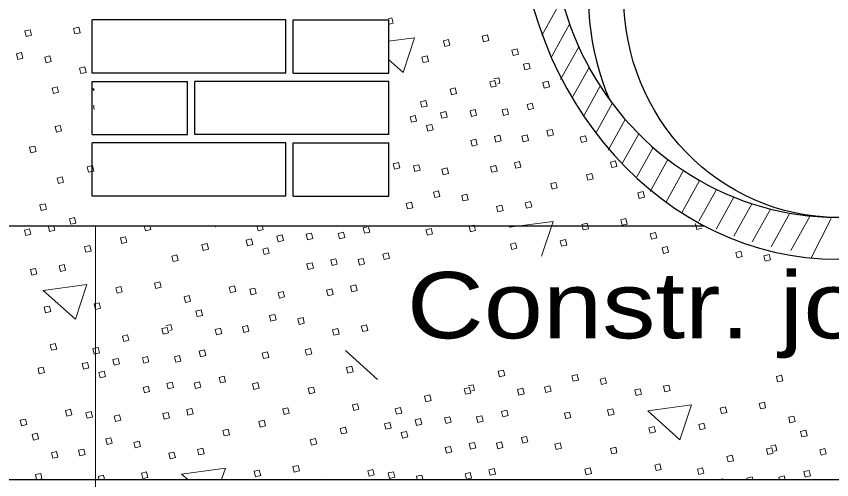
# Model space of a CAD drawing. Extents: x 750.7 to 784.7, y 860.1 to 882.1.
# Drawn here: x 761.813 to 763.779, y 862.952 to 864.07 of the extents above; entities that cross this region are included whole.
import ezdxf

# ---------------------------------------------------------------- set-up
doc = ezdxf.new("R2010")
doc.units = 0
doc.header["$LTSCALE"] = 0.064
doc.layers.add('1', color=7, linetype='Continuous', lineweight=13)

msp = doc.modelspace()

# ---------------------------------------------------------------- linework, layer by layer
at = {"layer": '1'}
for p, q in [((763.07975, 864.02367), (763.12817, 864.11092)), ((762.70967, 864.06392), (762.71867, 864.06608)), ((763.10242, 863.97033), (763.14692, 864.0505)), ((762.77325, 864.01792), (762.7095, 864.0095)), ((763.125, 863.91692), (763.16892, 863.996)), ((763.15492, 863.87667), (763.19367, 863.94642)), ((762.96383, 863.91883), (762.97592, 863.92167)), ((763.18183, 863.83092), (763.22075, 863.901)), ((763.21008, 863.78758), (763.24992, 863.85933)), ((763.23958, 863.74658), (763.28092, 863.82108)), ((763.274, 863.7145), (763.31367, 863.78592)), ((763.30875, 863.68283), (763.34808, 863.75367)), ((763.34125, 863.64733), (763.384, 863.72425)), ((763.37892, 863.621), (763.4215, 863.6975)), ((763.41792, 863.597), (763.46042, 863.6735)), ((763.45825, 863.5755), (763.50083, 863.65217)), ((763.49992, 863.55633), (763.54283, 863.63358)), ((763.54292, 863.53958), (763.58625, 863.61775)), ((763.58733, 863.52542), (763.63133, 863.60475)), ((763.63317, 863.51383), (763.67808, 863.59475)), ((763.107, 863.57508), (763.00158, 863.561)), ((763.07917, 863.49133), (763.107, 863.57508)), ((763.68058, 863.505), (763.72667, 863.58808)), ((763.72958, 863.48683), (763.77717, 863.582)), ((762.00408, 862.95208), (762.00408, 863.56433)), ((762.17367, 863.32342), (762.18583, 863.32625)), ((762.6065, 863.26333), (762.68408, 863.19367)), ((762.9025, 863.17825), (762.91458, 863.18108)), ((762.00408, 863.15042), (762.00408, 862.09025)), ((763.63125, 863.033), (763.64342, 863.03592)), ((762.02317, 862.96258), (762.02567, 862.95208)), ((762.30775, 862.95208), (762.31692, 862.97967)), ((762.79025, 862.96317), (762.79292, 862.95208)), ((762.55975, 862.95208), (762.56375, 862.953)), ((762.56375, 862.953), (762.564, 862.95208)), ((763.50742, 862.95208), (763.51608, 862.95417)), ((763.51608, 862.95417), (763.51658, 862.95208)), ((763.58708, 862.95883), (763.58867, 862.95208)), ((763.66417, 862.96108), (763.66633, 862.95208))]:
    msp.add_line(p, q, dxfattribs=at)
at = {"layer": '1', "lineweight": 25}
for p, q in [((762.71083, 863.93283), (762.71083, 864.06083)), ((762.48075, 863.93283), (762.71083, 863.93283)), ((762.22558, 863.7845), (762.22558, 863.91258)), ((761.9955, 863.7845), (762.22558, 863.7845)), ((762.71083, 863.63625), (762.71083, 863.76433)), ((762.48075, 863.63625), (762.71083, 863.63625)), ((760.59067, 863.56433), (763.47158, 863.56433)), ((760.59067, 862.95208), (765.58325, 862.95208))]:
    msp.add_line(p, q, dxfattribs=at)
at = {"layer": '1'}
for points in [[(762.71867, 864.06608), (762.72183, 864.05283), (762.70967, 864.04992)], [(762.70942, 863.96658), (762.74542, 863.93425), (762.77325, 864.01792)], [(762.97592, 863.92167), (762.97908, 863.90842), (762.97275, 863.90692)], [(762.00033, 863.89517), (761.99625, 863.89458), (762.00042, 863.89083)], [(762.00092, 863.84533), (761.99883, 863.85392), (762.00083, 863.85433)], [(761.9035, 863.5625), (761.90567, 863.55367), (761.89308, 863.55067), (761.89025, 863.5625)], [(762.1355, 863.56217), (762.13717, 863.55508), (762.12467, 863.55208), (762.12225, 863.56217)], [(762.29325, 863.56192), (762.29275, 863.56183), (762.29267, 863.56192)], [(762.40683, 863.56175), (762.40833, 863.5555), (762.39575, 863.55258), (762.39358, 863.56175)], [(762.66208, 863.56142), (762.665, 863.54933), (762.65242, 863.54633), (762.64925, 863.55958), (762.65692, 863.56142)], [(763.46592, 863.55875), (763.4535, 863.55583), (763.45033, 863.569), (763.45133, 863.56925)], [(762.18583, 863.32625), (762.189, 863.31308), (762.18267, 863.3115)], [(762.91458, 863.18108), (762.91775, 863.16783), (762.91142, 863.16633)], [(763.64342, 863.03592), (763.64658, 863.02267), (763.64025, 863.02108)], [(761.862, 862.95208), (761.85908, 862.96417), (761.87167, 862.96717)], [(761.87167, 862.96717), (761.87483, 862.95392), (761.86717, 862.95208)], [(762.01242, 862.95208), (762.01058, 862.95958), (762.02317, 862.96258)], [(762.31692, 862.97967), (762.2115, 862.96558), (762.2265, 862.95208)], [(762.77958, 862.95208), (762.77767, 862.96025), (762.79025, 862.96317)], [(763.57542, 862.95208), (763.5745, 862.95583), (763.58708, 862.95883)], [(763.65308, 862.95208), (763.65167, 862.95808), (763.66417, 862.96108)]]:
    msp.add_lwpolyline(points, dxfattribs=at)
at = {"layer": '1', "lineweight": 25}
for points in [[(762.46308, 863.93283), (762.46308, 864.06083), (761.99542, 864.06083)], [(762.46308, 863.93283), (761.99542, 863.93283), (761.99542, 864.06083)], [(762.48075, 863.93283), (762.48075, 864.06083), (762.71083, 864.06083)], [(761.9955, 863.7845), (761.9955, 863.91258), (762.22558, 863.91258)], [(762.71083, 863.7845), (762.71083, 863.91258), (762.24317, 863.91258)], [(762.71083, 863.7845), (762.24317, 863.7845), (762.24317, 863.91258)], [(762.46308, 863.63625), (762.46308, 863.76433), (761.99542, 863.76433)], [(762.46308, 863.63625), (761.99542, 863.63625), (761.99542, 863.76433)], [(762.48075, 863.63625), (762.48075, 863.76433), (762.71083, 863.76433)]]:
    msp.add_lwpolyline(points, dxfattribs=at)
at = {"layer": '1'}
for points in [[(761.84625, 864.03733), (761.84942, 864.02417), (761.83683, 864.02117), (761.83367, 864.03442)], [(761.9635, 864.04333), (761.96667, 864.03008), (761.95417, 864.02708), (761.95092, 864.04033)], [(762.94892, 864.02467), (762.95208, 864.01142), (762.93958, 864.00842), (762.93633, 864.02167)], [(762.85525, 864.01342), (762.85842, 864.00017), (762.84592, 863.99725), (762.84267, 864.01042)], [(763.02017, 863.99133), (763.02333, 863.97808), (763.01075, 863.97508), (763.00758, 863.98833)], [(761.82575, 863.98208), (761.829, 863.96892), (761.81642, 863.96592), (761.81325, 863.97908)], [(761.89392, 863.97408), (761.89708, 863.96083), (761.88458, 863.95783), (761.88133, 863.97108)], [(762.80317, 863.97425), (762.80642, 863.961), (762.79383, 863.958), (762.79067, 863.97125)], [(761.97792, 863.94775), (761.98108, 863.9345), (761.96858, 863.9315), (761.96533, 863.94475)], [(763.04867, 863.957), (763.05183, 863.94375), (763.03925, 863.94075), (763.03608, 863.954)], [(762.96683, 863.91483), (762.97, 863.90158), (762.95742, 863.89858), (762.95425, 863.91183)], [(763.09517, 863.913), (763.09833, 863.89975), (763.08575, 863.89675), (763.08258, 863.91)], [(761.91175, 863.89967), (761.915, 863.88642), (761.90242, 863.8835), (761.89925, 863.89667)], [(762.87133, 863.89692), (762.8745, 863.88367), (762.86192, 863.88067), (762.85875, 863.89392)], [(762.80017, 863.8665), (762.80342, 863.85325), (762.79083, 863.85025), (762.78767, 863.8635)], [(763.05683, 863.86025), (763.06, 863.847), (763.0475, 863.844), (763.04425, 863.85725)], [(762.77475, 863.83042), (762.77792, 863.81717), (762.76533, 863.81417), (762.76217, 863.82742)], [(762.84858, 863.83992), (762.85175, 863.82667), (762.83925, 863.82367), (762.836, 863.83692)], [(762.91958, 863.84458), (762.92275, 863.83133), (762.91025, 863.82833), (762.907, 863.84158)], [(762.99675, 863.84692), (762.99992, 863.83367), (762.98733, 863.83067), (762.98417, 863.84392)], [(762.81475, 863.80908), (762.81792, 863.79583), (762.80542, 863.79283), (762.80217, 863.80608)], [(761.91892, 863.80667), (761.92217, 863.7935), (761.90958, 863.7905), (761.90642, 863.80375)], [(763.1045, 863.797), (763.10775, 863.78375), (763.09517, 863.78075), (763.092, 863.794)], [(762.92108, 863.773), (762.92433, 863.75975), (762.91175, 863.75683), (762.90858, 863.77)], [(762.97867, 863.78267), (762.98183, 863.76942), (762.96925, 863.76642), (762.96608, 863.77967)], [(763.04442, 863.78358), (763.04758, 863.77033), (763.035, 863.76733), (763.03183, 863.78058)], [(763.18533, 863.78158), (763.1885, 863.76833), (763.17592, 863.76533), (763.17275, 863.77858)], [(761.8575, 863.75675), (761.86067, 863.7435), (761.84808, 863.7405), (761.84492, 863.75375)], [(761.99633, 863.70975), (761.99958, 863.69658), (761.987, 863.69358), (761.98383, 863.70683)], [(762.73408, 863.71725), (762.73725, 863.704), (762.72475, 863.701), (762.7215, 863.71425)], [(762.78342, 863.71183), (762.78658, 863.69858), (762.77408, 863.69558), (762.77083, 863.70883)], [(762.96883, 863.70975), (762.972, 863.6965), (762.95942, 863.6935), (762.95625, 863.70675)], [(763.02633, 863.71942), (763.0295, 863.70617), (763.017, 863.70317), (763.01375, 863.71642)], [(763.25783, 863.72083), (763.26108, 863.70758), (763.2485, 863.70467), (763.24533, 863.71783)], [(762.85158, 863.70383), (762.85475, 863.69058), (762.84217, 863.68758), (762.839, 863.70083)], [(763.20033, 863.69058), (763.20358, 863.67733), (763.191, 863.67433), (763.18783, 863.68758)], [(761.92375, 863.68267), (761.927, 863.66942), (761.91442, 863.66642), (761.91117, 863.67967)], [(763.11383, 863.66917), (763.117, 863.65592), (763.1045, 863.65292), (763.10125, 863.66617)], [(762.83108, 863.6485), (762.83433, 863.63533), (762.82175, 863.63233), (762.81858, 863.64558)], [(762.89925, 863.6405), (762.90242, 863.62725), (762.88983, 863.62425), (762.88667, 863.6375)], [(763.32417, 863.64675), (763.32733, 863.6335), (763.31475, 863.6305), (763.31158, 863.64375)], [(761.88225, 863.61767), (761.8855, 863.60442), (761.87292, 863.60142), (761.86975, 863.61467)], [(762.76558, 863.62125), (762.76875, 863.608), (762.75625, 863.60508), (762.753, 863.61825)], [(762.98325, 863.61417), (762.98642, 863.60092), (762.97383, 863.59792), (762.97067, 863.61117)], [(763.05242, 863.62317), (763.05558, 863.60992), (763.043, 863.607), (763.03983, 863.62017)], [(761.9535, 863.58433), (761.95667, 863.57108), (761.94417, 863.56808), (761.94092, 863.58133)], [(763.28267, 863.58175), (763.28583, 863.5685), (763.27333, 863.56558), (763.27008, 863.57875)], [(761.84492, 863.55725), (761.84817, 863.544), (761.83558, 863.541), (761.83242, 863.55425)], [(762.81325, 863.558), (762.8165, 863.54475), (762.80392, 863.54175), (762.80067, 863.555)], [(762.91708, 863.56608), (762.92033, 863.55292), (762.90775, 863.54992), (762.90458, 863.56317)], [(763.189, 863.57058), (763.19217, 863.55733), (763.17958, 863.55433), (763.17642, 863.56758)], [(762.0765, 863.53808), (762.07967, 863.52483), (762.06717, 863.52183), (762.06392, 863.53508)], [(762.37967, 863.53267), (762.38283, 863.51942), (762.37033, 863.51642), (762.36708, 863.52967)], [(762.4535, 863.54225), (762.45675, 863.529), (762.44417, 863.526), (762.441, 863.53925)], [(762.5245, 863.54692), (762.52767, 863.53367), (762.51517, 863.53067), (762.51192, 863.54392)], [(762.60167, 863.54917), (762.60483, 863.53592), (762.59225, 863.53292), (762.58908, 863.54617)], [(763.35392, 863.54842), (763.35708, 863.53517), (763.3445, 863.53217), (763.34133, 863.54542)], [(761.98992, 863.51667), (761.99317, 863.50342), (761.98058, 863.50042), (761.97742, 863.51367)], [(762.27292, 863.52142), (762.27608, 863.50817), (762.2635, 863.50517), (762.26033, 863.51842)], [(763.01675, 863.52333), (763.01992, 863.51008), (763.00742, 863.50708), (763.00417, 863.52033)], [(763.13692, 863.53133), (763.14017, 863.51808), (763.12758, 863.51508), (763.12442, 863.52833)], [(763.38242, 863.51408), (763.38558, 863.50083), (763.373, 863.49783), (763.36983, 863.51108)], [(762.20025, 863.49425), (762.2035, 863.481), (762.19092, 863.478), (762.18775, 863.49125)], [(762.41967, 863.51142), (762.42292, 863.49817), (762.41033, 863.49517), (762.40717, 863.50842)], [(762.7095, 863.49925), (762.71267, 863.486), (762.70008, 863.48308), (762.69692, 863.49625)], [(763.55992, 863.50333), (763.56308, 863.49008), (763.55058, 863.48708), (763.54733, 863.50033)], [(763.628, 863.49533), (763.63125, 863.48208), (763.61867, 863.47908), (763.6155, 863.49233)], [(762.52608, 863.47533), (762.52925, 863.46208), (762.51667, 863.45908), (762.5135, 863.47233)], [(762.58358, 863.485), (762.58675, 863.47175), (762.57425, 863.46875), (762.571, 863.482)], [(762.64933, 863.48592), (762.6525, 863.47267), (762.64, 863.46967), (762.63675, 863.48292)], [(761.85933, 863.46167), (761.86258, 863.44842), (761.85, 863.44542), (761.84683, 863.45867)], [(761.9285, 863.47067), (761.93175, 863.45742), (761.91917, 863.45442), (761.916, 863.46767)], [(761.98317, 863.4225), (761.87775, 863.4085), (761.95525, 863.33883)], [(762.06508, 863.41808), (762.06833, 863.40483), (762.05575, 863.40183), (762.05258, 863.41508)], [(762.15875, 863.42925), (762.162, 863.416), (762.14942, 863.413), (762.14625, 863.42625)], [(762.339, 863.4195), (762.34217, 863.40625), (762.32967, 863.40325), (762.32642, 863.4165)], [(762.63125, 863.42167), (762.6345, 863.40842), (762.62192, 863.40542), (762.61875, 863.41867)], [(762.23, 863.39592), (762.23325, 863.38267), (762.22067, 863.37967), (762.2175, 863.39292)], [(762.38833, 863.41408), (762.39158, 863.40092), (762.379, 863.39792), (762.37583, 863.41117)], [(762.4565, 863.40608), (762.45967, 863.39283), (762.44708, 863.38983), (762.44392, 863.40308)], [(762.57375, 863.412), (762.57692, 863.39883), (762.56442, 863.39583), (762.56117, 863.40908)], [(762.01308, 863.37883), (762.01625, 863.36558), (762.00375, 863.36258), (762.0005, 863.37583)], [(761.89292, 863.37083), (761.89608, 863.35758), (761.8835, 863.35458), (761.88033, 863.36783)], [(762.2585, 863.36158), (762.26175, 863.34833), (762.24917, 863.34533), (762.246, 863.35858)], [(762.436, 863.35083), (762.43925, 863.33758), (762.42667, 863.33458), (762.4235, 863.34783)], [(762.50417, 863.34283), (762.50733, 863.32958), (762.49483, 863.32658), (762.49158, 863.33983)], [(762.17667, 863.31942), (762.17992, 863.30617), (762.16733, 863.30317), (762.16408, 863.31642)], [(762.305, 863.31758), (762.30817, 863.30433), (762.29567, 863.30142), (762.29242, 863.31458)], [(762.3705, 863.32358), (762.37367, 863.31033), (762.36117, 863.30733), (762.35792, 863.32058)], [(762.58817, 863.3165), (762.59133, 863.30325), (762.57883, 863.30025), (762.57558, 863.3135)], [(762.65733, 863.3255), (762.6605, 863.31225), (762.648, 863.30925), (762.64475, 863.3225)], [(762.08117, 863.3015), (762.08433, 863.28825), (762.07183, 863.28525), (762.06858, 863.2985)], [(761.907, 863.28033), (761.91025, 863.26708), (761.89767, 863.26408), (761.89442, 863.27733)], [(762.01008, 863.27108), (762.01325, 863.25783), (762.00075, 863.25483), (761.9975, 863.26808)], [(762.26675, 863.26483), (762.26992, 863.25167), (762.25733, 863.24867), (762.25417, 863.26192)], [(762.41817, 863.26025), (762.42142, 863.24708), (762.40883, 863.24408), (762.40567, 863.25733)], [(762.522, 863.26842), (762.52525, 863.25517), (762.51267, 863.25217), (762.5095, 863.26542)], [(762.0585, 863.2445), (762.06167, 863.23125), (762.04908, 863.22825), (762.04592, 863.2415)], [(762.12942, 863.24917), (762.13267, 863.23592), (762.12008, 863.23292), (762.11692, 863.24617)], [(762.20658, 863.2515), (762.20975, 863.23825), (762.19725, 863.23525), (762.194, 863.2485)], [(761.87783, 863.22367), (761.881, 863.21042), (761.86842, 863.20742), (761.86525, 863.22067)], [(761.98458, 863.235), (761.98783, 863.22175), (761.97525, 863.21875), (761.972, 863.232)], [(762.62167, 863.22558), (762.62492, 863.21233), (762.61233, 863.20933), (762.60917, 863.22258)], [(762.02467, 863.21367), (762.02783, 863.2005), (762.01525, 863.1975), (762.01208, 863.21075)], [(762.31442, 863.20158), (762.31758, 863.18833), (762.305, 863.18533), (762.30183, 863.19858)], [(762.98733, 863.21642), (762.9905, 863.20317), (762.978, 863.20017), (762.97475, 863.21342)], [(763.16483, 863.20567), (763.168, 863.19242), (763.1555, 863.18942), (763.15225, 863.20267)], [(763.65792, 863.20383), (763.66108, 863.19058), (763.6485, 863.18767), (763.64533, 863.20083)], [(762.1885, 863.18725), (762.19175, 863.174), (762.17917, 863.171), (762.176, 863.18425)], [(762.25425, 863.18817), (762.2575, 863.17492), (762.24492, 863.172), (762.24175, 863.18517)], [(762.39517, 863.18617), (762.39842, 863.17292), (762.38583, 863.16992), (762.38258, 863.18317)], [(763.233, 863.19758), (763.23617, 863.18442), (763.22358, 863.18142), (763.22042, 863.19467)], [(763.38617, 863.18033), (763.38933, 863.16708), (763.37675, 863.16408), (763.37358, 863.17733)], [(762.131, 863.17758), (762.13417, 863.16442), (762.12167, 863.16142), (762.11842, 863.17467)], [(762.52917, 863.17542), (762.53242, 863.16217), (762.51983, 863.15917), (762.51667, 863.17242)], [(762.9055, 863.17425), (762.90867, 863.161), (762.89608, 863.158), (762.89292, 863.17125)], [(763.03383, 863.17242), (763.037, 863.15917), (763.02442, 863.15617), (763.02125, 863.16942)], [(763.09933, 863.17842), (763.1025, 863.16517), (763.08992, 863.16217), (763.08675, 863.17542)], [(763.317, 863.17133), (763.32017, 863.15808), (763.30758, 863.15508), (763.30442, 863.16833)], [(762.81, 863.15633), (762.81317, 863.14308), (762.80058, 863.14008), (762.79742, 863.15333)], [(761.94392, 863.12183), (761.94717, 863.10858), (761.93458, 863.10558), (761.93142, 863.11883)], [(762.23625, 863.124), (762.23942, 863.11075), (762.22683, 863.10775), (762.22367, 863.121)], [(762.46775, 863.1255), (762.47092, 863.11225), (762.45842, 863.10925), (762.45517, 863.1225)], [(762.63583, 863.13517), (762.639, 863.12192), (762.6265, 863.11892), (762.62325, 863.13217)], [(762.73892, 863.12592), (762.74208, 863.11267), (762.7295, 863.10967), (762.72633, 863.12292)], [(762.9955, 863.11967), (762.99875, 863.10642), (762.98617, 863.10342), (762.98292, 863.11667)], [(763.25083, 863.12325), (763.254, 863.11), (763.2415, 863.107), (763.23825, 863.12025)], [(763.44075, 863.13217), (763.33533, 863.11817), (763.41292, 863.04842)], [(763.52275, 863.12767), (763.52592, 863.11442), (763.51333, 863.11142), (763.51017, 863.12467)], [(763.61642, 863.13892), (763.61958, 863.12567), (763.607, 863.12267), (763.60383, 863.13592)], [(761.99325, 863.11642), (761.9965, 863.10317), (761.98392, 863.10017), (761.98075, 863.11342)], [(762.06142, 863.10842), (762.06458, 863.09517), (762.05208, 863.09217), (762.04883, 863.10542)], [(762.17867, 863.11433), (762.18192, 863.10108), (762.16933, 863.09808), (762.16617, 863.11133)], [(762.85825, 863.104), (762.86142, 863.09075), (762.84892, 863.08775), (762.84567, 863.101)], [(762.93542, 863.10633), (762.93858, 863.09308), (762.926, 863.09008), (762.92283, 863.10333)], [(763.147, 863.11508), (763.15017, 863.10183), (763.13767, 863.09883), (763.13442, 863.11208)], [(763.68767, 863.10558), (763.69083, 863.09233), (763.67825, 863.08933), (763.67508, 863.10258)], [(761.835, 863.09825), (761.83817, 863.085), (761.82558, 863.082), (761.82242, 863.09525)], [(762.41025, 863.09517), (762.41342, 863.08192), (762.40092, 863.07892), (762.39767, 863.09217)], [(762.71342, 863.08975), (762.71658, 863.07658), (762.704, 863.07358), (762.70083, 863.08683)], [(762.78725, 863.09933), (762.7905, 863.08608), (762.77792, 863.08308), (762.77475, 863.09633)], [(763.3505, 863.08042), (763.35367, 863.06717), (763.34117, 863.06417), (763.33792, 863.07742)], [(763.47067, 863.08842), (763.47392, 863.07525), (763.46133, 863.07225), (763.45808, 863.0855)], [(761.8635, 863.06383), (761.86667, 863.05067), (761.85408, 863.04767), (761.85092, 863.06092)], [(762.32367, 863.07375), (762.32692, 863.0605), (762.31433, 863.05758), (762.31117, 863.07075)], [(762.60658, 863.0785), (762.60983, 863.06525), (762.59725, 863.06225), (762.59408, 863.0755)], [(762.75342, 863.0685), (762.75658, 863.05525), (762.74408, 863.05225), (762.74083, 863.0655)], [(763.71617, 863.07117), (763.71933, 863.058), (763.70675, 863.055), (763.70358, 863.06825)], [(762.041, 863.05317), (762.04417, 863.03992), (762.03158, 863.03692), (762.02842, 863.05017)], [(762.10908, 863.04508), (762.11233, 863.03183), (762.09975, 863.02883), (762.09658, 863.04208)], [(762.534, 863.05133), (762.53725, 863.03808), (762.52467, 863.03508), (762.5215, 863.04833)], [(762.91733, 863.04208), (762.9205, 863.02883), (762.908, 863.02583), (762.90475, 863.03908)], [(762.98308, 863.043), (762.98625, 863.02975), (762.97375, 863.02675), (762.9705, 863.04)], [(763.04317, 863.05642), (763.04642, 863.04317), (763.03383, 863.04017), (763.03067, 863.05342)], [(763.124, 863.041), (763.12717, 863.02775), (763.11458, 863.02475), (763.11142, 863.038)], [(761.97542, 863.02592), (761.97867, 863.01267), (761.96608, 863.00967), (761.96292, 863.02292)], [(762.26225, 863.02783), (762.2655, 863.01458), (762.25292, 863.01158), (762.24967, 863.02483)], [(762.85983, 863.03242), (762.863, 863.01917), (762.85042, 863.01617), (762.84725, 863.02942)], [(763.258, 863.03025), (763.26117, 863.017), (763.24867, 863.014), (763.24542, 863.02725)], [(763.63425, 863.029), (763.6375, 863.01583), (763.62492, 863.01283), (763.62175, 863.02608)], [(763.76258, 863.02725), (763.76583, 863.014), (763.75325, 863.011), (763.75008, 863.02425)], [(761.90992, 863.01992), (761.91317, 863.00667), (761.90058, 863.00367), (761.89742, 863.01692)], [(762.19308, 863.01875), (762.19633, 863.0055), (762.18375, 863.0025), (762.18058, 863.01575)], [(763.53875, 863.01108), (763.542, 862.99783), (763.52942, 862.99492), (763.52625, 863.00808)], [(762.4925, 862.98642), (762.49575, 862.97317), (762.48317, 862.97017), (762.48, 862.98342)], [(763.36458, 862.99), (763.36783, 862.97675), (763.35525, 862.97375), (763.35208, 862.987)], [(762.127, 862.97075), (762.13017, 862.9575), (762.11758, 862.9545), (762.11442, 862.96775)], [(762.39883, 862.97517), (762.40208, 862.96192), (762.3895, 862.95892), (762.38625, 862.97217)], [(762.67275, 862.97667), (762.67592, 862.96342), (762.66342, 862.96042), (762.66017, 862.97367)], [(762.72208, 862.97125), (762.72525, 862.958), (762.71275, 862.955), (762.7095, 862.96825)], [(762.9075, 862.96917), (762.91067, 862.95592), (762.89817, 862.95292), (762.89492, 862.96617)], [(762.965, 862.97883), (762.96817, 862.96558), (762.95567, 862.96258), (762.95242, 862.97583)], [(763.19658, 862.98025), (763.19975, 862.967), (763.18717, 862.964), (763.184, 862.97725)], [(763.46767, 862.98075), (763.47092, 862.9675), (763.45833, 862.9645), (763.45508, 862.97775)], [(763.72433, 862.9745), (763.7275, 862.96125), (763.71492, 862.95825), (763.71175, 862.9715)]]:
    msp.add_lwpolyline(points, close=True, dxfattribs=at)
at = {"layer": '1', "lineweight": 25}
for centre, major_axis, ratio, start_param, end_param in [((763.79367, 864.11909), (0, -0.62258), 0.966184, 2.6512367, 5.125903), ((763.79367, 864.37492), (0, -0.89117), 0.869565, 4.747022, 7.8193474), ((763.79367, 864.29853), (0, 0.71385), 0.966184, 1.5331043, 4.7385268)]:
    msp.add_ellipse(centre, major_axis=major_axis, ratio=ratio, start_param=start_param, end_param=end_param, dxfattribs=at)
msp.add_ellipse((763.79367, 864.11909), major_axis=(0, 0.53442), ratio=0.966184, dxfattribs=at)

# ---------------------------------------------------------------- texts
at = {"layer": '1', "width": 1.2}
msp.add_text('Constr. joint', height=0.16, dxfattribs=at).set_placement((762.7545, 863.293))

doc.saveas('drawing.dxf')
